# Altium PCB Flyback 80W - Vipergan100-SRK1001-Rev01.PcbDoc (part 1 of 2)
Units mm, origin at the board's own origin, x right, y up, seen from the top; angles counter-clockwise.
Board outline 121.92 x 39.12 mm, 2 copper layers (Top Layer, Bottom Layer), stack 1.58 mm thick; 100 components, 56 nets, 249 pads, 157 vias.
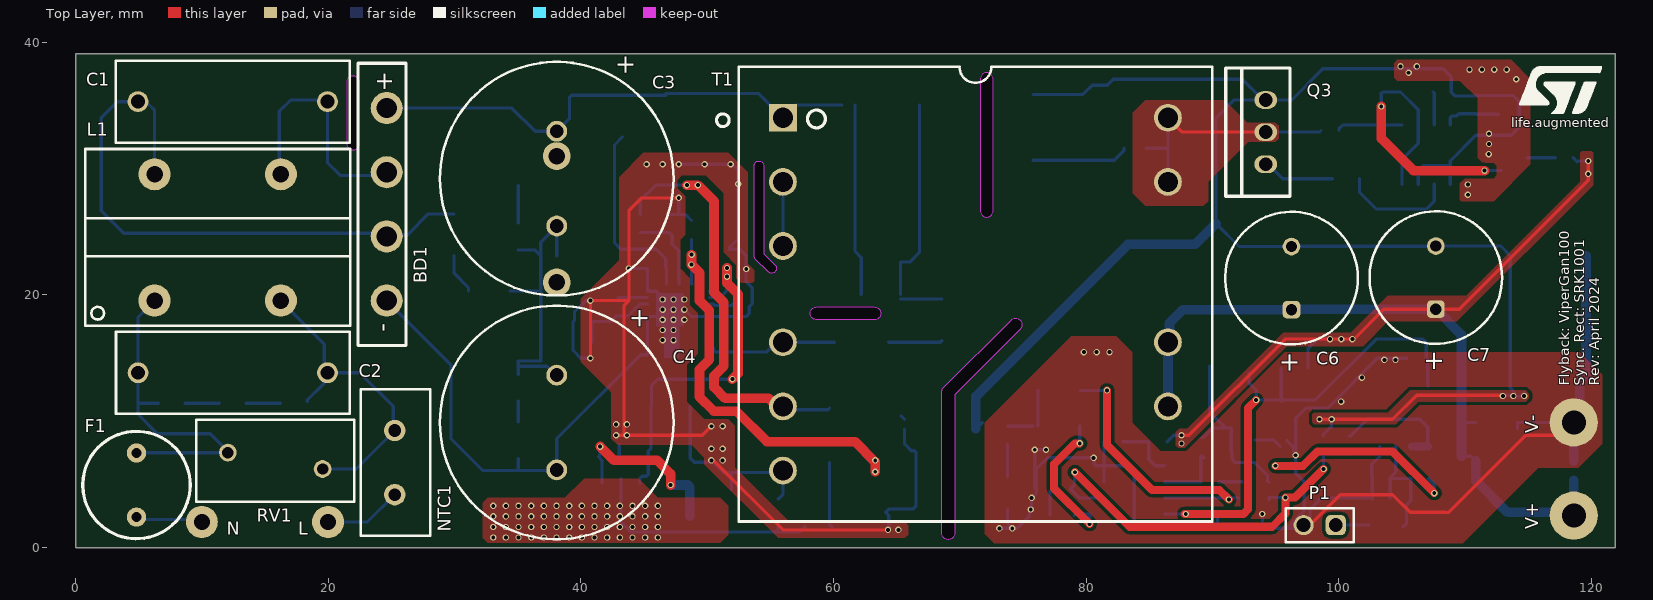
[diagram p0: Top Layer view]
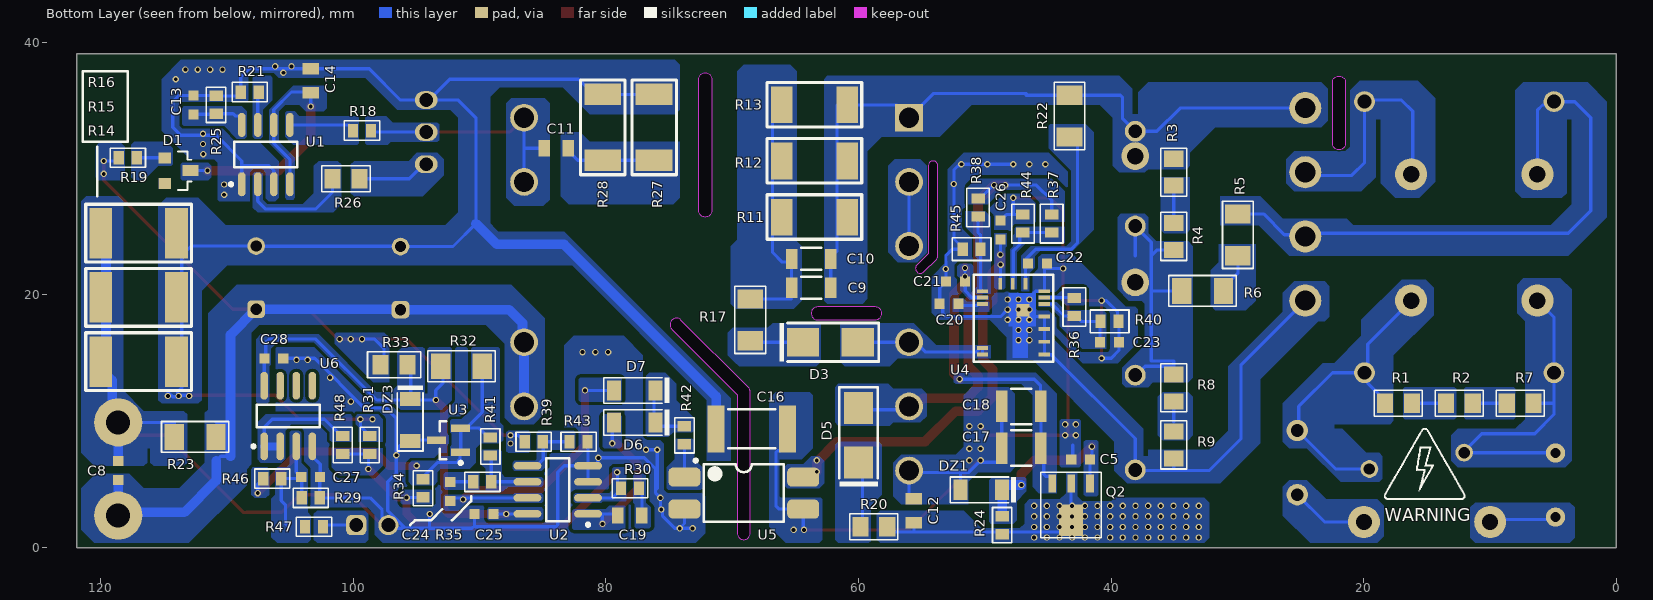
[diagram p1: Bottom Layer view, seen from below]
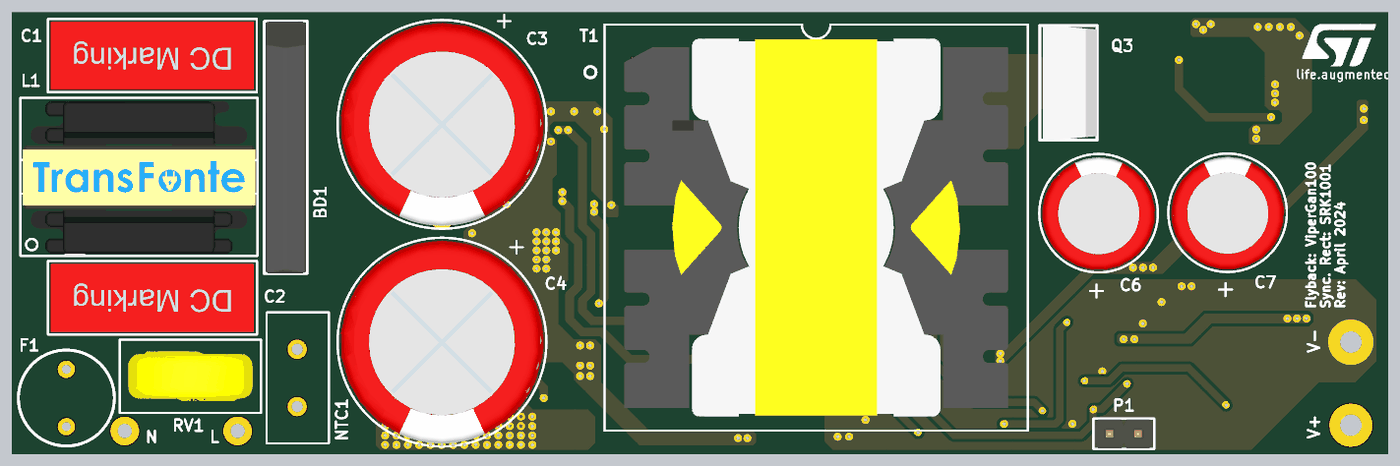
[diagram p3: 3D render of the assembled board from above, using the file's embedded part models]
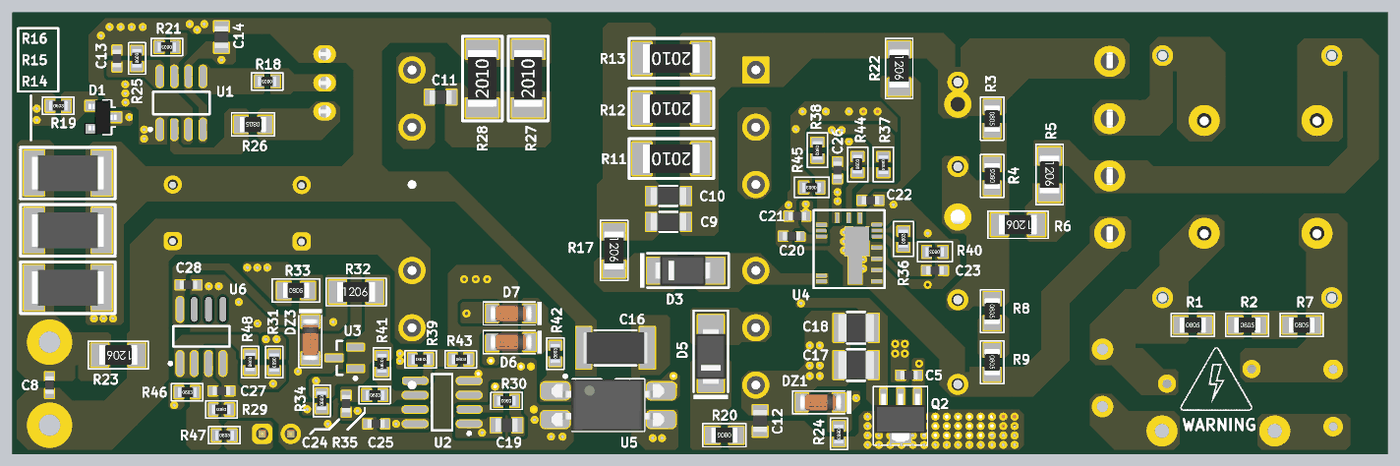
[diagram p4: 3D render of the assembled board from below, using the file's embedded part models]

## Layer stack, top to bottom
Top Solder: solder mask 0.0102, Solder Resist, Dk 3.5
Top Layer: signal copper 0.07
Dielectric 1: dielectric 1.44, FR-4, Dk 4.8
Bottom Layer: signal copper 0.07
Bottom Solder: solder mask 0.0102, Solder Resist, Dk 3.5

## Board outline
0,0 0,39.116 121.92,39.116 121.92,0
cut-out: 53.833,22.844 cw(c54.102,23.114) 53.721,23.114 53.721,30.226 cw(c54.102,30.226) 54.483,30.226 54.483,23.272 55.388,22.368 cw(c55.118,22.098) 55.499,22.098 cw(c55.118,22.098) 54.848,21.828
cut-out: 68.58,1.143 68.58,12.319 cw(c69.088,12.319) 68.729,12.679 68.729,12.678 74.063,18.012 cw(c74.422,17.653) 74.93,17.653 cw(c74.422,17.653) 74.781,17.294 69.596,12.108 69.596,1.143 cw(c69.088,1.143)
cut-out: 71.628,26.67 ccw(c72.136,26.67) 72.644,26.67 72.644,37.084 ccw(c72.136,37.084) 71.628,37.084
cut-out: 21.463,32.004 ccw(c21.971,32.004) 22.479,32.004 22.479,36.83 ccw(c21.971,36.83) 21.463,36.83
cut-out: 58.674,18.034 cw(c58.674,18.542) 58.674,19.05 63.246,19.05 cw(c63.246,18.542) 63.754,18.542 cw(c63.246,18.542) 63.246,18.034

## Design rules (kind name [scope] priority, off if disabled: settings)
Clearance Aux [InNet('Aux')] p1: gap=0.127 ignorepadtopadclearanceinfootprint=FALSE except(0: THPad-Hole Via-Hole Fill-Hole Poly-Hole Region-Hole Text-Hole; 0.305: Track-Poly Poly-Poly)
Clearance GND_Sec [InNet('GND-Sec')] p2: gap=0.203 ignorepadtopadclearanceinfootprint=TRUE except(0: THPad-Hole Via-Hole Fill-Hole Poly-Hole Region-Hole Text-Hole; 0.254: Arc-Poly Track-Poly SMDPad-Poly THPad-Poly Via-Poly Fill-Poly Poly-Poly Poly-Region Poly-Text)
Clearance GND_Out [InNet('GND-Out')] p3: gap=0.203 ignorepadtopadclearanceinfootprint=TRUE except(0: THPad-Hole Via-Hole Fill-Hole Region-Hole Text-Hole; 0.254: Arc-Poly Track-Poly SMDPad-Poly THPad-Poly Via-Poly Fill-Poly Poly-Poly Poly-Region Poly-Text Poly-Hole)
Clearance GND_Prim [InNet('GND-prim')] p4: gap=0.152 ignorepadtopadclearanceinfootprint=TRUE except(0: SMDPad-Hole THPad-Hole Via-Hole Fill-Hole Poly-Hole Region-Hole Text-Hole; 0.203: Track-Poly; 0.254: Poly-Poly)
Clearance Drain_PFC [InNet('Drain_PFC')] p5: gap=0.127 ignorepadtopadclearanceinfootprint=TRUE except(0: SMDPad-Hole THPad-Hole Via-Hole Fill-Hole Poly-Hole Region-Hole Text-Hole; 0.178: SMDPad-SMDPad; 0.203: SMDPad-Poly THPad-Poly Via-Poly Fill-Poly; 0.762: Arc-Track Arc-SMDPad Arc-THPad Arc-Poly Track-Track Track-SMDPad Track-THPad Track-Poly Poly-Poly)
Clearance Drain_Viper [InNet('Drain_Viper')] p6: gap=0.127 ignorepadtopadclearanceinfootprint=TRUE except(0: SMDPad-Hole THPad-Hole Via-Hole Fill-Hole Poly-Hole Region-Hole Text-Hole; 0.178: SMDPad-SMDPad; 0.203: Arc-Poly Track-Poly SMDPad-Poly THPad-Poly Via-Poly Fill-Poly Poly-Poly; 1.27: Arc-SMDPad Track-SMDPad)
Clearance [All] p7: gap=0.127 ignorepadtopadclearanceinfootprint=TRUE except(0: THPad-Hole Via-Hole Fill-Hole Poly-Hole Region-Hole Text-Hole)
Height [All] p1: minheight=0 maxheight=40 prefheight=26
MinimumSolderMaskSliver [All] p1: minsoldermaskwidth=0.076
PolygonConnect [All] p1: connectstyle=Direct reliefconductorwidth=0.254 reliefentries=4 polygonreliefangle="90 Angle" airgapwidth=0.254
RoutingVias [All] p1: holewidth=0.711 width=1.27 viastyle="Through Hole" minholewidth=0.305 minwidth=0.508 maxholewidth=0.711 maxwidth=1.27
SilkToSilkClearance [All] p1: silktosilkclearance=0.127
SilkToSolderMaskClearance [IsPad] p1: minsilkscreentomaskgap=0.076 clearancetoexposedcopper=TRUE
SolderMaskExpansion [All] p1: expansion=0.102 istentingtop=FALSE
Width [All] p1: maxlimit=0.762 minlimit=0.127 preferedwidth=0.254 minimp=50.000000 maximp=50.000000 favimp=50.000000
26 further rules are at their usual default settings.

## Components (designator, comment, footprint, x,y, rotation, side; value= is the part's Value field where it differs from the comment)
BD1 "4A/800V" GBU806 24.638,27.178 r270 top
C1 "220nF, 275V" WCAP-FTX2_L18W6H11.5 12.446,35.306 r180 top
C2 "220nF, 275V" WCAP-FTX2_L18W6H11.5 12.453,13.843 r180 top
C3 "150uF, 200V" WCAP-AT1H_18x25 38.1,29.21 r90 top locked
C4 "150uF, 200V" WCAP-AT1H_18x25 38.1,9.906 r90 top locked
C5 "NM" WCAP-CSGP_0603_H=0.8mm_Reflow 42.418,6.985 r180 bottom
C6 "330uF" WCAP-PTG5_D10H12.5 96.266,21.336 r270 top
C7 "330uF" WCAP-PTG5_D10H12.5 107.696,21.376 r270 top
C8 "100nF, 50V" WCAP-CSGP_0603_H=0.8mm_Reflow 118.618,6.096 r270 bottom
C9 "2.2nF, 630V" WCAP-CSMH_1206_H1.6 63.754,20.574 r180 bottom
C10 "2.2nF, 630V" WCAP-CSMH_1206_H1.6 63.754,22.86 r180 bottom
C11 "NM" WCAP-CSGP_0805_H=0.8mm_Reflow 83.947,31.623 r0 bottom
C12 "1nF, 200V" WCAP-CSMH_0805_H1.25 55.626,2.921 r270 bottom
C13 "NM" WCAP-CSGP_0603_H=0.8mm_Reflow 112.649,35.052 r270 bottom
C14 "1uF, 25V" WCAP-CSGP_0805_H=1.25mm 103.378,36.957 r270 bottom
C16 "2.2nF, 250V" WCAP-CSSA_2211_H2.5 68.453,9.398 r0 bottom
C17 "22uF, 25V" WCAP-CSGP_1210_H=2.5mm 47.117,7.874 r180 bottom
C18 "22uF, 25V" WCAP-CSGP_1210_H=2.5mm 47.117,11.176 r180 bottom
C19 "47nF, 25V" WCAP-CSGP_0805_H=0.8mm_Reflow 78.105,2.54 r0 bottom
C20 "1uF, 16V" WCAP-CSGP_0603_H=0.8mm_Reflow 52.832,19.304 r180 bottom
C21 "100nF, 50V" WCAP-CSGP_0603_H=0.8mm_Reflow 52.324,21.082 r180 bottom
C22 "220pF, 50V" WCAP-CSGP_0603_H=0.8mm_Reflow 45.847,22.479 r0 bottom
C23 "10nF, 25V" WCAP-CSGP_0603_H=0.8mm_Reflow 40.132,16.256 r0 bottom
C24 "220nF, 25V" WCAP-CSGP_0603_H=0.8mm_Reflow 92.329,4.445 r90 bottom
C25 "100nF, 50V" WCAP-CSGP_0603_H=0.8mm_Reflow 89.662,2.667 r180 bottom
C26 "4.7nF, 25V" WCAP-CSGP_0603_H=0.8mm_Reflow 48.768,25.146 r270 bottom
C27 "470nF, 25V" WCAP-CSGP_0603_H=0.8mm_Reflow 103.378,5.588 r0 bottom
C28 "100nF, 50V" WCAP-CSGP_0603_H=0.8mm_Reflow 106.3,14.986 r0 bottom
D1 "BAS21" SOT23_Single 113.919,29.845 r270 bottom value=250V/200mA
D3 "STTH2L06A" SMA 62.23,16.256 r180 bottom value=1A/600V
D5 "STTH1L06A" SMA 60,8.89 r90 bottom value=1A/600V
D6 "LL4148" SOD80 77.724,9.906 r0 bottom value="100V 150mA"
D7 "LL4148" SOD80 77.724,12.446 r0 bottom value="100V 150mA"
DZ1 "TZM5245B-GS08" SOD80 50.292,4.572 r0 bottom value=15V/0.5W
DZ3 "NM" SOD80 95.504,10.1 r270 bottom
F1 "4A/250Vac" MRT 4.826,4.953 r90 top
L "Line" Pin_Hole_50mil 20,2.032 r0 top
L1 "YEF20V-4P10MH" EF20VCD4T-F 6.256,19.558 r90 top
N "Neutral" Pin_Hole_50mil 10,2.032 r0 top
NTC1 "2.2Ω" D11.5xW5.0xH16.0xL5.0 25.273,6.731 r90 top value="2.2Ω, 6 / 5A"
P1 "61300211121" 61300211121 98.5,1.778 r180 top
Q2 "ZXTN4006ZTA" "SOT-89 - BCE" 43.18,5.08 r0 bottom value=200V/1A
Q3 "FDP075N15A_F102" NFET_TO220FP 94.234,30.353 r90 top
R1 "TBD" 0805 17.272,11.43 r180 bottom
R2 "TBD" 0805 12.446,11.43 r180 bottom
R3 "1M5 ± 5%" 0805 35.052,29.718 r270 bottom
R4 "1M5 ± 5%" 0805 35.052,24.638 r90 bottom
R5 "0R" 1206 29.972,24.765 r270 bottom
R6 "0R" 1206 32.766,20.32 r0 bottom
R7 "TBD" 0805 7.62,11.43 r180 bottom
R8 "1M5 ± 5%" 0805 35.052,12.649 r270 bottom
R9 "1M5 ± 5%" 0805 35.052,8.128 r270 bottom
R11 "470K ± 5%" 2010 63.5,26.162 r0 bottom
R12 "470K ± 5%" 2010 63.5,30.607 r0 bottom
R13 "470K ± 5%" 2010 63.5,35.052 r0 bottom
R14 "22 mOhm ±1%" 2512 117,14.732 r0 bottom
R15 "22 mOhm ±1%" 2512 117,19.812 r0 bottom
R16 "22 mOhm ±1%" 2512 117,24.892 r0 bottom
R17 "20R ± 1%" 1206 68.58,18.034 r270 bottom
R18 "330R ± 5%" "0603 - teste" 99.314,33.02 r0 bottom
R19 "0R" "0603 - teste" 117.856,30.861 r180 bottom
R20 "47R ± 5%" 0805 58.801,1.651 r0 bottom
R21 "75K ± 5%" "0603 - teste" 108.204,36.068 r0 bottom
R22 "10M ± 1%" 1206 43.307,34.163 r270 bottom
R23 "NM" 1206 112.522,8.763 r0 bottom
R24 "39K ± 5%" "0603 - teste" 48.641,1.778 r270 bottom
R25 "75K ± 5%" "0603 - teste" 110.871,35.052 r90 bottom
R26 "0R" 0805 100.584,29.21 r0 bottom
R27 "NM 2010" 2010 76.2,33.274 r90 bottom
R28 "NM 2010" 2010 80.264,33.274 r90 bottom
R29 "180K ± 5%" "0603 - teste" 103.378,3.937 r0 bottom
R30 "22K ± 5%" "0603 - teste" 78.105,4.699 r0 bottom
R31 "1K5 ± 1%" "0603 - teste" 98.7,8.128 r270 bottom
R32 "2K2 ± 5%" 1206 91.44,14.351 r180 bottom
R33 "0R" SM/R_0805 96.774,14.478 r180 bottom
R34 "1M ± 5%" "0603 - teste" 94.488,4.699 r90 bottom
R35 "47K ± 5%" "0603 - teste" 89.789,5.207 r180 bottom
R36 "61K9" SM/R_0603 42.926,19.05 r90 bottom
R37 "820K" SM/R_0603 44.704,25.654 r270 bottom
R38 "560K" SM/R_0603 50.546,26.924 r270 bottom
R39 "130K ± 1%" "0603 - teste" 85.725,8.382 r180 bottom
R40 "20K5" SM/R_0603 40.132,17.907 r0 bottom
R41 "10K ± 5%" "0603 - teste" 89.154,8.001 r90 bottom
R42 "1K ± 5%" "0603 - teste" 73.787,8.89 r90 bottom
R43 "18K2 ± 1%" "0603 - teste" 82.169,8.382 r180 bottom
R44 "15K" SM/R_0603 46.99,25.654 r90 bottom
R45 "15K" SM/R_0603 51.054,23.622 r0 bottom
R46 "NM ± 1%" "0603 - teste" 106.426,5.461 r180 bottom
R47 "1K ± 5%" "0603 - teste" 103.124,1.651 r180 bottom
R48 "26K1 ± 1%" "0603 - teste" 100.838,8.128 r90 bottom
RV1 "820512711" D12.5xW6.5xH16xP1.3 15.808,6.873 r0 top
T1 "YPQ3220V-12P435UH" PQ3220_Trigon 71.247,20.066 r0 top locked
U1 "SRK1001" SO8_L 106.934,31.115 r90 bottom
U2 "LM2904D" SO8_N 83.82,4.572 r0 bottom
U3 "TL431AIL3T" SOT23-3_N 92.456,8.509 r0 bottom
U4 "ViperGan100TR" "VIPERGAN - ISAC" 45.29,14.796 r0 bottom locked value="QR Controller"
U5 "FOD817AS" SO-4 69.088,4.318 r180 bottom
U6 "LM2904D" SO8_N 105.156,10.414 r90 bottom
V+ "Vout" Pin_Hole_75mil 118.618,2.54 r0 top
V- "GND" Pin_Hole_75mil 118.618,9.906 r0 top

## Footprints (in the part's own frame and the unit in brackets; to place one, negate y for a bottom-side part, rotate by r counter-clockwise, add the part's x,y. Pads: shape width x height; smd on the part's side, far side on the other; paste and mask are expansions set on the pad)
"0603 - teste" [mil] "SMD Chip Resistor, 125 mW, 0603 [1608 Metric], Thick Film, General Purpose"
  rect 32x42 smd: 1(-28,0) 2(28,0)
  silkscreen extent -55,-30 55,30, body extent -31,-17 33,17, height 16
0805 [mil] "SMD Chip Resistor, 200 mW, 0805 [2012 Metric], Thick Film, General Purpose"
  rect 50x60 smd: 1(-42,0) 2(42,0)
  silkscreen extent -75,-41 75,41, body extent -45,-27 45,27, height 30
1206 [mil] "SMD Chip Resistor, 250 mW, 1206 [3216 Metric], Thick Film, General Purpose"
  rect 60x80 smd: 1(-65,0) 2(65,0)
  silkscreen extent -105,-48 105,48, body extent -66,-34 66,34, height 33
2010 [mm] "'SMD Chip Resistor, 1W, 2010, Thick Film, General Purpose"
  rect 1.7x2.9 smd: 1(-2.6,0) 2(2.6,0)
  silkscreen extent -3.75,-1.78 3.75,1.75, body extent -2.5,-1.25 2.5,1.25, height 0.6
2512 [mm] "SMD Chip Resistor, 2W, 2512, Thick Film, General Purpose"
  rect 1.8x4 smd: 1(-2.997,0) 2(2.997,0)
  silkscreen extent -4.19,-2.29 4.19,2.29, body extent -3.17,-1.59 3.18,1.59, height 0.5
61300211121 [mm] "Pin Header, pitch 2.54 mm, THT, Vertical, single row, 2p"
  rrect50% 1.6x1.6 hole 1.1: 1(-1.27,0)
  round 1.6 hole 1.1: 2(1.27,0)
  silkscreen extent -2.69,-1.35 2.69,1.35, body extent -2.54,-1.27 2.54,1.27, height 8.57
D11.5xW5.0xH16.0xL5.0 [mm] "Inrush Current Limiter, Diameter 11.5mm, Width 5.0mm, Height 16.0mm, Leads 5.0mm"
  round 1.7 hole 1: 1(-2.54,0) 2(2.54,0)
  silkscreen extent -5.8,-2.8 5.8,2.7, body extent -5.75,-2.5 5.75,2.5, height 13.75
D12.5xW6.5xH16xP1.3 [mm] "Disk Varistor, Diameter 12.5mm, Width 6.5mm"
  round 1.4 hole 0.9: 1(-3.75,0.65) 2(3.75,-0.65)
  silkscreen extent -6.25,-3.25 6.25,3.25, body extent -5.5,-2.2 5.5,2.2, height 13.4
EF20VCD4T-F [mm]
  round 2.54 hole 1.3: 1(0,0) 2(0,-10) 3(10,-10) 4(10,0)
  silkscreen extent -2,-15.5 12,5.5, body extent -2,-15.3 11.7,5.3, height 21.48
GBU806 [mm]
  round 2.54 / inner round 1.524 / far side round 2.54 hole 1.6: 1(-7.62,0) 2(-2.54,0) 3(2.54,0) 4(7.62,0)
  silkscreen extent -11.18,-2.29 11.18,1.52, body extent -11.15,-2.16 11.15,1.4, height 20.83
MRT [mil]
  round 60 hole 31.5: 1(-100,0) 2(100,0)
  silkscreen extent -167,-167 167,167, body extent -165,-167 170,167, height 315
NFET_TO220FP [mm]
  oval 1.4x1.8 hole 1.1: D(2.54,0) G(0,0) S(5.08,0)
  silkscreen extent -2.54,-1.91 7.62,3.18, body extent -2.54,-1.91 7.62,2.89, height 19.3
Pin_Hole_50mil [mm]
  round 2.54 hole 1.27: 1(0,0)
Pin_Hole_75mil [mm]
  round 3.81 hole 1.905: 1(0,0)
PQ3220_Trigon [mm] "THT, Body 35.56x37.34mm, 12Pins,Pitch 5.08mm"
  rect 2.2x2.2 hole 1.6: 1(-15.24,13.97)
  round 2.2 hole 1.6: 2(-15.24,8.89) 3(-15.24,3.81) 4(-15.24,-3.81) 5(-15.24,-8.89) 6(-15.24,-13.97) 8(15.24,-8.89) 9(15.24,-3.81) 11(15.24,8.89) 12(15.24,13.97)
  silkscreen extent -20.5,-18 18.75,18, body extent -17,-16.75 17,16.75, height 20.92
SM/R_0603 [mil]
  rect 32x42 smd: 1(-28,0) 2(28,0)
  silkscreen extent -60,-36 60,35, body extent -31,-17 33,17, height 16
SM/R_0805 [mil]
  rect 50x60 smd: 1(-42,0) 2(42,0)
  silkscreen extent -83,-41 83,41, body extent -45,-26 45,27, height 30
SMA [mil]
  rect 100x90 smd: A(85,0) K(-85,0)
  silkscreen extent -159,-60 150,60, body extent -108,-53 88,53, height 95
SO8_L [mm] "SOIC, 8-Leads, Body 4.9x3.9mm, Pitch 1.27mm, IPC High Density"
  oval 1.9x0.6 smd: 1(-2.35,1.905) 2(-2.35,0.635) 3(-2.35,-0.635) 4(-2.35,-1.905) 5(2.35,-1.905) 6(2.35,-0.635) 7(2.35,0.635) 8(2.35,1.905)
  silkscreen extent -2.47,-2.5 1,2.88, body extent -2,-2.5 2,2.5, height 1.75
SO8_N [mm] "SOIC, 8-Leads, Body 4.9x3.9mm, Pitch 1.27mm, IPC Medium Density"
  oval 2.2x0.6 smd: 1(-2.4,1.905) 2(-2.4,0.635) 3(-2.4,-0.635) 4(-2.4,-1.905) 5(2.4,-1.905) 6(2.4,-0.635) 7(2.4,0.635) 8(2.4,1.905)
  silkscreen extent -2.52,-2.5 0.9,2.88, body extent -2,-2.5 2,2.5, height 1.75
SO-4 [mil]
  rrect50% 100x60 smd: 1(-185,50) 2(-185,-50) 3(185,-50) 4(185,50)
  silkscreen extent -155,-90 125,106, body extent -199,-90 195,90, height 152
SOD80 [mm] "LL4148"
  rect 1.1x1.6 smd: A(1.65,0) K(-1.65,0)
  silkscreen extent -2.74,-1.02 2.45,1.02, body extent -1.88,-0.8 1.82,0.8, height 1.6
SOT23-3_N [mm] "SOT23, 3-Leads, Body 2.9x1.3mm, Pitch 0.95mm, Lead Span 2.4mm, IPC Medium Density"
  rect 1.5x0.6 smd: 1(-0.95,0.95) 2(-0.95,-0.95) 3(0.95,0)
  silkscreen extent -1.07,-1.5 0.7,1.92, body extent -0.7,-1.52 0.7,1.52, height 1.12
SOT23_Single [mil]
  rect 34x40 smd: A(-40,-40) NC(40,-40)
  rect 34x50 smd: K(0,40)
  silkscreen extent -60,1 60,44, body extent -59,-49 59,49, height 42
"SOT-89 - BCE" [mm]
  rect 0.6x1.4 smd: B(-1.5,0) C(0,0) E(1.5,0)
  rect 1.9x2.5 smd: C(0,2.9)
  silkscreen extent -2.4,-0.9 2.4,4.3, body extent -2.25,-0.25 2.25,4, height 1.54
"VIPERGAN - ISAC" [mm]
  rect 0.9x0.3 smd mask+0.05: 1(0,-0.5) 2(0,-1.5) 3(0,-2.5) 4(0,-3.5) 5(0,-4.5) 6(0,-5) 7(0,-5.5) 11(4.9,-5.5) 12(4.9,-5) 13(4.9,-4.5) 15(4.9,-1) 16(4.9,-0.5)
  rect 0.3x0.9 smd mask+0.05: 8(1.5,-6.1) 9(2.5,-6.1) 10(3.5,-6.1)
  rect 1x1 smd paste+0: EP(1.7,-4)
  Top Layer region: 0.675,-5.341 2.829,-5.341 2.829,-2.741 2.524,-2.741 2.524,-0.241 1.3,-0.241 1.3,-2.741 0.675,-2.741
  silkscreen extent -0.7,-6.8 5.6,0.1, body extent 0,-6 5,0, height 0.58
WCAP-AT1H_18x25 [mm] "Aluminium Electrolytic Radial THD Capacitors, 18x25mm"
  round 1.65 hole 1.1: 1(-3.75,0) 2(3.75,0)
  silkscreen extent -9.25,-9.25 9.25,9.25, body extent -8.99,-9 9,9, height 25.26
WCAP-CSGP_0603_H=0.8mm_Reflow [mm] "Ceramic Capacitors, body 1.6x0.8mm"
  rect 0.8x0.8 smd: 1(-0.75,0) 2(0.75,0)
  body extent -0.8,-0.4 0.8,0.4, height 0.8
WCAP-CSGP_0805_H=0.8mm_Reflow [mm] "Ceramic Capacitors, body 2x1.25mm"
  rect 0.9x1.3 smd: 1(-0.95,0) 2(0.95,0)
  body extent -1,-0.62 1,0.63, height 0.8
WCAP-CSGP_0805_H=1.25mm [mm] "Ceramic Capacitors, body 2x1.25mm"
  rect 0.9x1.3 smd: 1(-0.95,0) 2(0.95,0)
  body extent -1,-0.62 1,0.63, height 1.25
WCAP-CSGP_1210_H=2.5mm [mm] "Ceramic Capacitors, body 3.2x2.5mm"
  rect 0.9x2.5 smd: 1(-1.55,0) 2(1.55,0)
  silkscreen extent -0.8,-1.4 0.8,1.4, body extent -1.6,-1.25 1.6,1.25, height 2.5
WCAP-CSMH_0805_H1.25 [mm] "Ceramic Capacitors, body 2x1.25mm"
  rect 0.9x1.3 smd: 1(-0.95,0) 2(0.95,0)
  body extent -1,-0.62 1,0.63, height 1.25
WCAP-CSMH_1206_H1.6 [mm] "Ceramic Capacitors, body 3.2x1.6mm"
  rect 0.9x1.6 smd: 1(-1.55,0) 2(1.55,0)
  silkscreen extent -0.8,-0.87 0.8,0.87, body extent -1.6,-0.8 1.6,0.8, height 1.6
WCAP-CSSA_2211_H2.5 [mm] "Ceramic Capacitors, body 5.7x2.8mm"
  rect 1.35x3.7 smd: 1(-2.825,0) 2(2.825,0)
  silkscreen extent -1.85,-1.55 1.85,1.55, body extent -2.85,-1.4 2.85,1.4, height 2.5
WCAP-FTX2_L18W6H11.5 [mm] "Film Capacitors, 18x6x11.5mm"
  round 1.65 hole 1.1: 1(-7.5,0) 2(7.5,0)
  silkscreen extent -9.25,-3.25 9.25,3.25, body extent -9,-3 9,3, height 11.55
WCAP-PTG5_D10H12.5 [mm] "Aluminum Polymer Capacitors, 10x12.5mm"
  rrect50% 1.4x1.4 hole 0.9: 1(2.5,0)
  round 1.4 hole 0.9: 2(-2.5,0)
  silkscreen extent -5.25,-5.25 5.25,5.25, body extent -4.95,-4.99 5,4.99, height 12.81

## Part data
BD1: library part GBU806, "800V 4A GBL Single Phase Bridge Rectifier", Forward Current=4A, Manufacturer="Diodes Inc", Manufacturer Part Number=GBU8J, Max Forward Surge Current (Ifsm)=150A, Max Operating Temperature=150°C, Max Repetitive Reverse Voltage (Vrrm)=800V, Max Reverse Current=5uA, Min Operating Temperature=-55°C, Package Quantity=1000, Package/Class="Full wave bridge", Supplier Part Number 1=GBU806DI-ND
C1 C2: library part 890324025027, "WCAP-FTX2 Film Capacitor, THT, L18W6H11.5, 220nF, 275V", Capacitance=220nF, Capacitance Tolerance=+/-10%, Insulation Resistance=30000MOhm, Manufacturer="Wurth Elektronik", Operating Temperature="-40 to +105degC", Rate of Voltage Rise=180V/us, Rated Voltage=275VAC
C3 C4: library part 860241081008, "WCAP-AT1H Aluminum Electrolytic Capacitor, Radial, THT, D18xH25mm, 150uF, 200V", Capacitance=150uF, Capacitance Tolerance=+/-20%, Leakage Current=1300uA, Manufacturer="Wurth Elektronik", Operating Temperature="-25 to +105degC", Rated Voltage=200VDC, Ripple Current=1800mA
C5 C8 C21 C25 C28: library part 885012206095, "WCAP-CSGP Multilayer Ceramic Chip Capacitor, General Purpose, size 0603, X7R, 100nF, 50V", Capacitance=100nF, Capacitance Tolerance=+/-10%, Isolation Resistance=>{}5GOhm, Manufacturer="Wurth Elektronik", Operating Temperature="-55 to +125degC", Rated Voltage=50VDC
C6 C7: library part 870025575009, "WCAP-PTG5 Aluminum Polymer Capacitor, Radial THT, D10xH12.5mm, 330uF, 25V", Capacitance Tolerance=+/-20%, Leakage Current=1650uA, Manufacturer="Wurth Elektronik", Operating Temperature Max=105°C, Operating Temperature Min=-55°C, Rated Voltage (DC)=25V, Ripple Current=4900mA
C9 C10: library part 885342008007, "WCAP-CSMH Multilayer Ceramic Chip Capacitor, size 1206, NP0 Class I, 2.2nF, 630V", Capacitance=2.2nF, Capacitance Tolerance=+/-5%, Insulation Resistance=10GOhm, Manufacturer="Wurth Elektronik", Operating Temperature="-55 to +125degC", Rated Voltage=630VDC
C11: library part 885012207119, "WCAP-CSGP Multilayer Ceramic Chip Capacitor, General Purpose, size 0805, X7R, 3.3nF, 100V", Capacitance=3.3nF, Capacitance Tolerance=+/-10%, Isolation Resistance=>{}10GOhm, Manufacturer="Wurth Elektronik", Operating Temperature="-55 to +125degC", Rated Voltage=100VDC
C12: library part 885342007003, "WCAP-CSMH Multilayer Ceramic Chip Capacitor, size 0805, NP0 Class I, 1nF, 200V", Capacitance=1nF, Capacitance Tolerance=+/-5%, Insulation Resistance=10GOhm, Manufacturer="Wurth Elektronik", Operating Temperature="-55 to +125degC", Rated Voltage=200VDC
C13: library part 885012206071, "WCAP-CSGP Multilayer Ceramic Chip Capacitor, General Purpose, size 0603, X7R, 100nF, 25V", Capacitance=100nF, Capacitance Tolerance=+/-10%, Isolation Resistance=>{}5GOhm, Manufacturer="Wurth Elektronik", Operating Temperature="-55 to +125degC", Rated Voltage=25VDC
C14: library part 885012207078, "WCAP-CSGP Multilayer Ceramic Chip Capacitor, General Purpose, size 0805, X7R, 1uF, 25V", Capacitance=1uF, Capacitance Tolerance=+/-10%, Isolation Resistance=>{}0.5GOhm, Manufacturer="Wurth Elektronik", Operating Temperature="-55 to +125degC", Rated Voltage=25VDC
C16: library part 885352213015, "WCAP-CSSA Multilayer Ceramic Chip Safety Capacitor, size 2211, X1/Y2, 2.2nF, 250V", Capacitance=2.2nF, Capacitance Tolerance=+/-10%, Impulse Voltage=5000VDC, Isolation Resistance=10GOhm, Manufacturer="Wurth Elektronik", Operating Temperature="-55 to +125degC", Rated Voltage=250VAC
C17 C18: library part 885012209074, "WCAP-CSGP Multilayer Ceramic Chip Capacitor, General Purpose, size 1210, X7R, 22uF, 25V", Capacitance=22uF, Capacitance Tolerance=+/10%, Isolation Resistance=>{}0.005GOhm, Manufacturer="Wurth Elektronik", Operating Temperature="-55 to +125degC", Rated Voltage=25VDC
C19: library part 885012207070, "WCAP-CSGP Multilayer Ceramic Chip Capacitor, General Purpose, size 0805, X7R, 47nF, 25V", Capacitance=47nF, Capacitance Tolerance=+/-10%, Isolation Resistance=>{}10GOhm, Manufacturer="Wurth Elektronik", Operating Temperature="-55 to +125degC", Rated Voltage=25VDC
C20: library part 885012106017, "WCAP-CSGP Multilayer Ceramic Chip Capacitor, General Purpose, size 0603, X5R, 1uF, 16V", Capacitance=1uF, Capacitance Tolerance=+/-20%, Isolation Resistance=>{}0.1GOhm, Manufacturer="Wurth Elektronik", Operating Temperature="-55 to +85degC", Rated Voltage=16VDC
C22: library part 885012206079, "WCAP-CSGP Multilayer Ceramic Chip Capacitor, General Purpose, size 0603, X7R, 220pF, 50V", Capacitance=220pF, Capacitance Tolerance=+/-10%, Isolation Resistance=>{}10GOhm, Manufacturer="Wurth Elektronik", Operating Temperature="-55 to +125degC", Rated Voltage=50VDC
C23: library part 885012206065, "WCAP-CSGP Multilayer Ceramic Chip Capacitor, General Purpose, size 0603, X7R, 10nF, 25V", Capacitance=10nF, Capacitance Tolerance=+/-10%, Isolation Resistance=>{}10GOhm, Manufacturer="Wurth Elektronik", Operating Temperature="-55 to +125degC", Rated Voltage=25VDC
C24 C27: library part 885012206075, "WCAP-CSGP Multilayer Ceramic Chip Capacitor, General Purpose, size 0603, X7R, 470nF, 25V", Capacitance=470nF, Capacitance Tolerance=+/-10%, Isolation Resistance=>{}1.1GOhm, Manufacturer="Wurth Elektronik", Operating Temperature="-55 to +125degC", Rated Voltage=25VDC
C26: library part 885012206063, "WCAP-CSGP Multilayer Ceramic Chip Capacitor, General Purpose, size 0603, X7R, 4.7nF, 25V", Capacitance=4.7nF, Capacitance Tolerance=+/-10%, Isolation Resistance=>{}10GOhm, Manufacturer="Wurth Elektronik", Operating Temperature="-55 to +125degC", Rated Voltage=25VDC
D1: "Fast Switching Diode.", Manufacturer=Diodes, Package=SOT-23
D3: library part SMA, "600 V, 2 A Low Drop Ultrafast Diode.", Manufacturer=STMicroelectronics
D5: library part SMA, "600 V, 1 A Low Drop Ultrafast Diode.", Manufacturer=STMicroelectronics
D6 D7: "Small Signal Diode", Manufacturer=Vishay, Manufacturer Part Number=LL4148-M-18, Package=SOD123
DZ1: library part TZM52xxB, "Small Signal Zener Diodes, 5%, 500mW", Manufacturer=Vishay, Package=SOD-80
DZ3: library part SOD80_zener
F1: library part Fuse, "FUSE BOARD MOUNT 4A 250VAC RAD", Case/Package=Radial, Color=Brown, Current Rating=4A, DC Cold Resistance=18.52mR, Flammability Rating="UL94 V-0", Manufacturer="Littelfuse Wickmann", Manufacturer Part Number=37314000410, Max Operating Temperature=85°C, Min Operating Temperature=-40°C, Package Quantity=1000, Power Dissipation=520mW, Supplier Part Number 1=WK3062BK-ND, Voltage Rating (AC)=250V
L N: library part Pin_Hole_50mil
L1: library part EF20VCD4T-F_Transfonte_Esquema2, Manufacturer="Trigon Components"
NTC1: library part B57236S0229M000, "Inrush Current Limiter, Diameter 11.5mm, Width 5.0mm, Height 16.0mm, Leads 5.0mm, 2.2Ω, 6 / 5A", Manufacturer=TDK, Max. Current="6 / 5A", Resistance Tolerance=±20%
P1: "WR-PHD Pin Header, THT, Vertical, pitch 2.54mm, 1 Row, 2P", Contact Resistance=20mΩ, Manufacturer="Wurth Elektronik", Operating Temperature Max=105°C, Operating Temperature Min=-40°C, Rated Current=3A, Withstanding Voltage=500V, Working Voltage=250V
Q2: library part NPN, "200V, 1A NPN LED DRIVING TRANSISTOR IN SOT89", Manufacturer=Diodes, Package=SOT89
Q3: library part NFET, "N-Channel Mosfet, 150V, 130A, 7.5m Ohms.", Manufacturer=ONSEMI, Package=TO-220
R1 R2 R3 R4 R7 R8 R9 R20 R26: library part 0805, "SMD Chip Resistor, 200 mW, 0805 [2012 Metric], Thick Film, General Purpose", Manufacturer=Any, Resistor Type="FIXED RESISTOR"
R5 R6 R17 R23 R32: library part 1206, "SMD Chip Resistor, 250 mW, 1206 [3216 Metric], Thick Film, General Purpose", Manufacturer=Any, Resistor Type="FIXED RESISTOR"
R11 R12 R13: library part 2010, "SMD Chip Resistor, 1W, 2010, Thick Film, General Purpose", Manufacturer=Yageo, Manufacturer Part Number=RC2010JK-07470KL, Resistor Type="FIXED RESISTOR"
R14 R15 R16: library part 2512, "SMD Chip Resistor, 2512, High Power Metal Strip Resistors for Current Sensing.", Manufacturer="TE Connectivity", Manufacturer Part Number=TLRP3A30DR022FTE, Resistor Type="FIXED RESISTOR"
R18: library part 0603, "SMD Chip Resistor, 125 mW,  0603 [1608 Metric] 330 Ohm, Thick Film, General Purpose", Manufacturer=Any, Resistor Type="FIXED RESISTOR"
R19 R21 R24 R25 R29 R30 R31 R34 R35 R39 R41 R42 R43 R46 R47 R48: library part 0603, "SMD Chip Resistor, 125 mW, 0603 [1608 Metric], Thick Film, General Purpose", Manufacturer=Any, Resistor Type="FIXED RESISTOR"
R22: library part 1206, "SMD Chip Resistor, 250 mW, 1206 [3216 Metric], Thick Film, General Purpose", Manufacturer=Bourns, Manufacturer Part Number=CHV1206-FX-1005ELF, Resistor Type="FIXED RESISTOR"
R27 R28: library part 2010, "SMD Chip Resistor, 1W, 2010, Thick Film, General Purpose", Manufacturer=Any, Resistor Type="FIXED RESISTOR"
R33: library part SMRes, "Res Thick Film 1206 10 Ohm 1% 1/4W ±100ppm/°C Molded SMD SMD Paper T/R", Case Code (Imperial)=1206, Case Code (Metric)=3216, Manufacturer Part Number=CRCW1206-10R0FKEA, Max Operating Temperature=155°C, Max Power Dissipation=250mW, Min Operating Temperature=-55°C, Package Quantity=10, Resistance=10R, Resistance Tolerance=1%, Resistor Type="FIXED RESISTOR", Supplier Part Number 1=52X0976, Temperature Coefficient=100ppm/°C, Voltage Rating=200V
R36: library part SMRes, "Res Thick Film 0603 61.9K Ohm 1% 1/10W ±100ppm/°C Molded SMD SMD Paper T/R", Case Code (Imperial)=0603, Case Code (Metric)=1608, Manufacturer=Any, Manufacturer Part Number=CRCW060356K0FKEA, Max Operating Temperature=155°C, Max Power Dissipation=100mW, Min Operating Temperature=-55°C, Package Quantity=10, Resistance=61.9K, Resistance Tolerance=1%, Resistor Type="FIXED RESISTOR", Supplier Part Number 1=6790548, Temperature Coefficient=100ppm/°C, Voltage Rating=75V
R37: library part SMRes, "Res Thick Film 0603 180K Ohm 1% 1/10W ±100ppm/°C Molded SMD SMD Paper T/R", Case Code (Imperial)=0603, Case Code (Metric)=1608, Manufacturer Part Number=CRCW0603180KFKEA, Max Operating Temperature=155°C, Max Power Dissipation=100mW, Min Operating Temperature=-55°C, Package Quantity=10, Resistance=180kR, Resistance Tolerance=1%, Resistor Type="FIXED RESISTOR", Temperature Coefficient=100ppm/°C, Voltage Rating=75V
R38: library part SMRes, "Res Thick Film 0603 120K Ohm 1% 0.1W(1/10W) ±100ppm/°C Pad SMD Automotive T/R", Case Code (Imperial)=0603, Case Code (Metric)=1608, Manufacturer Part Number=CRCW0603120KFKEA, Max Operating Temperature=155°C, Max Power Dissipation=100mW, Min Operating Temperature=-55°C, Package Quantity=5000, Resistance=120kR, Resistance Tolerance=1%, Resistor Type="FIXED RESISTOR", Supplier Part Number 1=6789715, Temperature Coefficient=100ppm/°C, Voltage Rating=75V
R40: library part SMRes, "Res Thick Film 0603 20.5K Ohm 1% 1/10W ±100ppm/°C Molded SMD Paper T/R", Case Code (Imperial)=0603, Case Code (Metric)=1608, Manufacturer=Any, Manufacturer Part Number=CRCW060315K0FKEA, Max Operating Temperature=155°C, Max Power Dissipation=100mW, Min Operating Temperature=-55°C, Package Quantity=5000, Resistance Tolerance=1%, Resistor Type="FIXED RESISTOR", Supplier Part Number 1=6789793, Temperature Coefficient=100ppm/°C, Voltage Rating=75V
R44 R45: library part SMRes, "Res Thick Film 0603 15K Ohm 1% 1/10W ±100ppm/°C Molded SMD Paper T/R", Case Code (Imperial)=0603, Case Code (Metric)=1608, Manufacturer Part Number=CRCW060315K0FKEA, Max Operating Temperature=155°C, Max Power Dissipation=100mW, Min Operating Temperature=-55°C, Package Quantity=5000, Resistance=15kR, Resistance Tolerance=1%, Resistor Type="FIXED RESISTOR", Supplier Part Number 1=6789793, Temperature Coefficient=100ppm/°C, Voltage Rating=75V
RV1: "WE-VD Disk Varistor, D12.5mm, W6.5mm, H16mm, 275VAC, 350VDC", (Channel) Input Capacitance=190pF, (Reverse) Breakdown Voltage=430V, (Reverse) Peak Pulse Current=2500A, AC Operating Voltage=275V, Clamping Voltage=710V, DC Operating Voltage=350V, Manufacturer="Wurth Elektronik", Operating Temperature="-40 to +85degC", Power Dissipation=0.4W
T1: library part "PQ3220, ViperGan100", "Transformer 12-Terminal , THT, Vertical, PQ Style Bobbins, PQ3220", Manufacturer="Trigon Components", Package=PQ3220
U1: "Adaptive synchronous rectification controller for flyback converter", Manufacturer=STMicroelectronics
U2 U6: "Low-Power Dual Operational Amplifier"
U3: "STMICROELECTRONICS - TL431AIL3T - Voltage Reference, AEC-Q100, Shunt - Adjustable, 2.5V to 36V, 1 % Ref, SOT-23-3", Case/Package=SOT-23-3, Cathode Current=700uA, Manufacturer=STMicroelectronics, Max Input Voltage=37V, Max Operating Temperature=105°C, Max Output Current=100mA, Max Output Voltage=36V, Min Operating Temperature=-40°C, Package Quantity=1, Reference Voltage=2.495V, Supplier Part Number 1=497-11295-1-ND, Tolerance=1%
U4: library part ViperGanxxx, "Advanced quasi-resonant offline high voltage converter with E-mode GaN HEMT.", Manufacturer=STMicroelectronics, Package=QFN5x6
U5: library part Optoisolator1, "Optocoupler DC-IN 1-CH Transistor DC-OUT 4-Pin PDIP SMD Black T/R", Case/Package=DIP, Collector Emitter Saturation Voltage=200mV, Current Transfer Ratio=160%, Forward Current=50mA, Forward Voltage=1.2V, Isolation Voltage=5kV, Manufacturer="Taiwan Semiconductor", Manufacturer Part Number="TPC817A C9G", Max Operating Temperature=100°C, Max Output Voltage=80V, Max Power Dissipation=200mW, Min Operating Temperature=-40°C, Output Voltage=70V, Package Quantity=1000, Reverse Breakdown Voltage=6V, Supplier Part Number 1=821-TPC817AC9G
V+ V-: library part Pin_Hole

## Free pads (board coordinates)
  round 2.2 hole 1.3: 2(38.1,21) 2(38.1,31)

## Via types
v1: diameter 0.508, hole 0.305, Top Layer to Bottom Layer, 157 vias

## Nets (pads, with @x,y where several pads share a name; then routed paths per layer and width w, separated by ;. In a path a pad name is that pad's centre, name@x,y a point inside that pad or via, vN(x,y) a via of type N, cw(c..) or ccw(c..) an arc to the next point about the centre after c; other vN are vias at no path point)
Aux: D5.A R37.1 R38.1 T1.5 | length 35.1
  Top Layer w0.762: v1(48.4,28.702) v1(49.276,28.702) 50.546,27.432 50.546,20.193 51.308,19.431 51.308,14.351 50.546,13.589 50.546,12.7 51.435,11.811 54.885,11.811 55.52,11.176 T1.5@56.007,11.176
  Bottom Layer w0.254: R37.1@44.704,26.365 44.704,27.485 45.921,28.702 v1(48.4,28.702) v1@48.514,28.702 ; v1(49.276,28.702) 49.352,28.702 50.419,27.635 R38.1@50.546,27.635 ; T1.5@56.007,11.176 56.261,10.922 59.563,10.922 D5.A@59.69,11.049
Drain_SR: C11.2 Q3.D R18.1 T1.11 T1.12 | length 20.1
  Top Layer w0.254: T1.11@86.487,28.956 T1.11@86.614,28.829 ; T1.12@86.487,34.036 87.63,32.893 Q3.D@94.234,32.893
  Bottom Layer w0.254: C11.2@84.77,31.623 86.418,31.623 86.487,31.554 ; T1.12@86.487,34.036 86.487,31.554 ; T1.11@86.571,28.872 T1.11@86.487,28.956 86.487,31.554 ; Q3.D@94.453,32.674 Q3.D@94.234,32.893 98.476,32.893 R18.1@98.603,33.02
Drain_Viper: D3.A T1.4 U4.15 U4.16 | length 10.9
  Bottom Layer w0.254: U4.16@50.19,15.296 U4.15@50.19,15.796 50.49,15.796 50.513,15.773 50.513,15.643 50.662,15.494 54.718,15.494 55.48,16.256 D3.A@60.071,16.256
FB: C26.2 U4.10 U5.4 | length 31.8
  Top Layer w0.762: v1@48.766,23.2 48.766,22.417 48.76,22.411 v1(48.76,22.405) 49.403,21.762 49.403,19.558 50.165,18.796 50.165,14.859 49.403,14.097 49.403,11.938 50.546,10.795 52.324,10.795 54.731,8.388 61.716,8.388 63.309,6.794 v1(63.309,6)
  Bottom Layer w0.254: v1(48.76,22.405) 48.775,22.39 48.775,20.911 U4.10@48.79,20.896 ; v1@48.76,23.14 48.76,24.388 C26.2@48.768,24.396
  other v1: 63.309,6.9 48.772,23.2
GND-Out: C8.1 C25.1 C27.1 C28.1 DZ3.A P1.2 R14.2 R15.2 R16.2 R23.2 R29.1 R43.2 U2.3 U2.4 U3.3 U5.2 U6.4 V-.1 | length 126.9
  Top Layer w0.254: P1.2@97.73,1.778 100.143,4.191 104.267,4.191 105.664,2.794 108.458,2.794 108.48,2.772 108.69,2.772 114.808,8.89 V-.1@118.618,8.89
  Bottom Layer w0.254: v1(73.148,1.524) v1(74.164,1.524) ; U5.2@73.787,3.048 73.787,1.905 74.164,1.528 v1(74.164,1.524) ; v1(76.835,7.747) v1(75.946,7.747) 75.946,6.223 75.946,4.699 76.073,4.572 ; U2.3@81.42,5.207 U2.4@81.42,6.477 ; R43.2@81.458,8.382 81.42,8.344 U2.4@81.42,6.477 ; C25.1@90.412,2.667 90.412,1.746 ; U3.3@93.406,8.509 94.869,8.509 DZ3.A@95.377,8.001 ; v1(93.956,2.66) 93.98,2.637 93.98,1.524 ; DZ3.A@95.885,8.485 96.012,8.358 96.014,8.358 96.437,7.935 96.437,7.576 ; U6.4@103.251,8.014 103.251,7.214 102.628,6.591 C27.1@102.628,5.588 102.667,5.549 R29.1@102.667,3.937 102.667,3.81 102.54,3.937 98.679,3.937 97.73,2.988 97.73,1.778 97.476,1.524 95.885,1.524 ; C28.1@105.422,14.986 104.382,14.986 103.62,14.986 103.071,14.986 99.134,11.049 97.409,11.049 96.598,10.238 v1(96.598,7.309) 96.598,5.891 97.282,5.207 97.282,2.921 95.885,1.524 ; R23.2@114.173,9.398 114.173,9.906 V-.1@118.618,9.906 ; v1(74.164,1.524) 74.549,1.524 75.516,2.491 75.516,3.017 75.692,3.193 v1(75.692,3.937) 76.073,4.318 76.073,4.572 ; 76.073,4.572 76.073,4.699 76.073,6.223 76.962,7.112 80.502,7.112 80.651,6.963 80.651,6.637 80.811,6.477 U2.4@81.42,6.477 ; U2.4@81.42,6.477 83.312,6.477 83.82,5.969 83.82,1.8 83.969,1.651 90.317,1.651 90.412,1.746 ; 90.412,1.746 90.634,1.524 93.98,1.524 ; 93.98,1.524 95.885,1.524
  Bottom Layer w0.762: V-.1@118.185,9.323 V-.1@118.618,8.89 ; C8.1@118.618,6.846 V-.1@118.618,8.89 ; R16.2@119.583,23.114 119.583,19.304 119.583,14.732 119.583,13.716 119.101,13.233 119.101,9.373 V-.1@118.618,8.89
  other v1: 75.62,3.017 80.605,7.105 100.191,11.556 101.842,13.461 103.62,14.858 104.5,14.858 79.828,15.481 80.844,15.481 81.86,15.481
GND-prim: BD1.4 C4.1 C5.1 C12.1 C16.1 C17.1 C18.1 C20.1 C21.1 C22.1 C23.1 C26.1 DZ1.A R9.2 R40.1 R44.2 R45.2 T1.6 U4.1 U4.2 U4.3 U4.4 U4.7 U4.EP U5.3 | length 162.9
  Top Layer w0.254: v1(40.767,14.986) v1(40.767,19.558) 43.815,19.558 ; 43.053,8.89 v1@43.434,8.89 ; v1(47.752,27.686) 44.831,27.686 43.815,26.67 v1(43.815,22.098) 43.815,19.558 ; v1(50.339,9.609) 49.62,8.89 v1@43.434,8.89 ; v1@50.423,6.984 56.01,1.397 v1@64.389,1.397 ; v1@43.434,8.89 43.434,19.177 43.815,19.558
  Bottom Layer w0.254: BD1.4@24.638,19.558 29.718,14.478 29.718,8.636 32.258,6.096 35.149,6.096 ; R9.2@35.052,7.061 35.052,6.193 35.149,6.096 ; v1(40.767,14.986) 40.005,14.986 39.382,15.609 C23.1@39.382,16.256 39.382,17.868 39.501,17.987 39.501,18.673 40.381,19.553 40.762,19.553 v1(40.767,19.558) ; 43.053,8.128 43.053,6.973 C5.1@43.168,6.858 ; v1(43.815,22.098) C22.1@45.224,22.098 ; C22.1@45.29,22.098 U4.7@45.29,20.296 45.998,20.296 46.617,19.677 46.617,19.169 U4.EP@46.99,18.796 ; R44.2@46.99,26.365 47.644,26.365 ; v1(47.752,27.686) 47.752,26.473 47.644,26.365 ; v1(47.752,30.353) v1(49.808,30.353) 51.932,30.353 52.053,30.232 52.133,30.232 52.451,29.914 52.451,24.435 51.765,23.749 R45.2@51.765,23.622 52.578,23.622 53.086,23.114 C21.1@53.086,21.082 ; C18.1@48.667,11.176 C17.1@48.667,7.874 48.667,7.074 48.99,6.751 50.479,6.751 51.278,5.952 51.943,5.952 ; C26.1@48.768,25.896 48.299,26.365 47.644,26.365 ; DZ1.A@51.942,4.572 51.942,5.951 51.943,5.952 ; C21.1@53.074,21.082 53.582,20.574 C20.1@53.582,19.304 53.34,19.062 53.34,18.542 53.086,18.288 48.768,18.288 48.26,18.796 U4.EP@46.99,18.796 ; C12.1@55.626,3.871 55.684,3.871 56.007,4.194 T1.6@56.007,6.096 55.863,5.952 51.943,5.952 ; v1@64.389,1.397 64.389,2.54 64.135,2.794 U5.3@64.389,3.048 66.294,3.048 66.548,3.302 66.548,7.526 66.399,7.675 66.176,7.675 65.628,8.223 C16.1@65.628,9.398 ; C16.1@65.374,10.414 C16.1@65.628,10.16 ; 35.149,6.096 38.04,6.096 C4.1@38.1,6.156 38.1,8.636 44.737,15.273 45.267,15.273 U4.1@45.29,15.296 U4.2@45.29,16.296 U4.3@45.29,17.296 U4.4@45.29,18.296 46.49,18.296 U4.EP@46.99,18.796
  other v1: 64.325,1.397 65.151,1.397 50.339,6.9 51.228,6.9 50.339,7.831 51.228,7.831 42.799,8.89 43.65,8.89 51.228,9.609 42.799,9.75 43.65,9.75 46.482,16.425 47.341,16.425 46.482,17.229 47.341,17.229 46.482,18.034 47.341,18.034 48.2,18.034 46.482,18.839 47.341,18.839 48.2,18.839 46.482,19.643 47.341,19.643 48.2,19.643 53.103,22.056 52.468,28.787 45.212,30.353 46.482,30.353 51.863,30.353
GND-Sec: C6.2 C7.2 C13.1 C14.1 C16.2 Q3.S R14.1 R15.1 R16.1 R21.2 R25.2 R27.2 R28.2 R31.1 U1.1 U1.3 | length 152
  Top Layer w0.254: v1(98.488,10.16) v1(99.441,10.16) 104.267,10.16 106.172,12.065 v1@113.157,12.065
  Bottom Layer w0.254: C16.2@71.278,9.398 C16.2@71.778,9.898 ; R27.2@75.819,35.874 79.756,35.874 80.479,36.597 81.682,36.597 82.169,37.084 92.383,37.084 Q3.S@94.034,35.433 ; R31.1@98.806,8.839 98.732,8.914 99.441,9.623 v1(99.441,10.16) ; U1.3@106.299,28.765 106.312,28.778 106.312,29.858 106.68,30.226 108.69,30.226 108.839,30.077 ; U1.1@108.839,28.765 108.839,30.077 ; v1@113.157,12.065 113.792,12.065 v1@113.919,11.938 ; 114.681,12.319 114.3,11.938 v1@113.919,11.938 ; Q3.S@94.034,35.433 Q3.S@94.234,35.433 96.266,35.433 98.74,37.907 C14.1@103.378,37.907 108.27,37.907 108.915,37.262 R21.2@108.915,36.068 108.915,36.043 109.195,35.763 R25.2@110.871,35.763 110.91,35.802 C13.1@112.649,35.802 113.804,35.802 114.3,35.306 114.3,33.274 113.665,32.639 111.904,32.639 110.871,32.639 108.839,30.607 108.839,30.077 ; Q3.S@94.034,35.433 91.694,35.433 90.297,34.036 90.297,25.654 92.115,23.836 C6.2@96.266,23.836 96.286,23.856 107.676,23.856 C7.2@107.696,23.876 112.827,23.876 113.589,23.114 113.589,19.304 113.589,14.732 113.589,12.649 113.919,12.319 113.919,12.065 v1@113.919,11.938
  Bottom Layer w0.762: C16.2@71.278,9.398 71.278,11.969 83.312,24.003 88.646,24.003 90.297,25.654
  other v1: 113,12 113.84,12 114.681,12 110.236,27.94 110.236,28.75 111.887,31.15 111.904,31.955 111.904,32.759 114.063,37.077 105.537,37.592 110.363,37.846 111.342,37.846 112.322,37.846 113.301,37.846 104.902,38.1 106.2,38.1
HV: C22.2 R22.2 U4.8 | length 15.2
  Bottom Layer w0.254: R22.2@43.307,32.512 42.672,31.877 42.672,24.13 43.18,23.622 45.974,23.622 46.736,22.86 46.736,22.152 46.79,22.098 U4.8@46.79,20.896
In-: R30.2 R31.2 R34.1 R48.1 U2.2 | length 33.5
  Top Layer w0.635: v1(79.121,5.969) 83.439,1.651 94.742,1.651 95.786,2.695 v1(95.786,3.955) 96.538,3.955 v1(98.806,6.223)
  Bottom Layer w0.254: v1(79.121,5.969) 79.096,5.944 79.096,4.978 R30.2@78.816,4.699 78.816,4.572 79.451,3.937 U2.2@81.42,3.937 ; R34.1@94.488,3.773 R34.1@94.488,3.988 94.52,3.955 v1(95.786,3.955) ; v1(98.806,6.223) 98.806,7.417 R48.1@101.092,7.417
NetBD1_2: BD1.2 C1.1 L1.3 | length 19.4
  Bottom Layer w0.254: L1.3@16.336,29.638 L1.3@16.256,29.558 16.129,29.685 16.129,34.544 17.018,35.433 19.819,35.433 C1.1@19.946,35.306 19.946,30.473 20.955,29.464 24.384,29.464 BD1.2@24.638,29.718
NetBD1_3: BD1.3 C1.2 L1.4 R5.1 | length 47.2
  Bottom Layer w0.254: L1.4@6.256,29.304 6.256,34.638 5.855,35.039 5.213,35.039 C1.2@4.946,35.306 3.302,35.306 2.032,34.036 2.032,26.67 3.81,24.892 24.384,24.892 BD1.3@24.638,24.638 24.765,24.765 26.289,24.765 27.94,26.416 R5.1@29.972,26.416
NetC2_1: C2.1 L1.2 NTC1.2 R1.1 RV1.2 | length 25.6
  Bottom Layer w0.254: L1.2@16.256,19.558 19.699,16.115 C2.1@19.699,13.589 ; R1.1@18.346,11.557 18.346,11.684 19.686,13.024 19.686,13.576 C2.1@19.699,13.589 ; RV1.2@19.558,6.223 22.225,6.223 NTC1.2@25.273,9.271 25.146,9.398 25.146,11.176 22.479,13.843 C2.1@19.953,13.843 19.764,13.654 C2.1@19.699,13.589
NetC2_2: C2.2 F1.2 L1.1 R7.2 RV1.1 | length 26.8
  Bottom Layer w0.254: F1.2@4.826,7.493 4.841,7.508 12.043,7.508 RV1.1@12.058,7.523 12.058,7.627 10.668,9.017 6.477,9.017 4.953,10.541 4.953,11.43 ; L1.1@6.256,19.558 4.953,18.255 C2.2@4.953,13.843 4.953,11.43 ; R7.2@6.553,11.43 4.953,11.43
NetC3_1: C3.1 C4.2 pad.2@38.1,21 R4.1 R6.2 R8.1 | length 24.1
  Bottom Layer w0.254: R6.2@34.417,20.32 36.83,20.32 ; R8.1@35.052,13.716 35.052,14.351 ; R4.1@35.052,23.571 36.373,23.571 36.83,23.114 ; C4.2@38.1,13.656 37.995,13.656 37.3,14.351 35.052,14.351 ; 38.1,23.114 C3.1@38.1,25.46 36.83,24.19 36.83,23.114 ; 35.052,14.351 35.052,14.783 36.83,14.783 36.83,20.32 ; 36.83,20.32 36.83,23.114
NetC5_2: C5.2 DZ1.K Q2.B R24.1 | length 14.3
  Top Layer w0.762: v1(41.529,8.001) 42.608,6.921 46.038,6.921 47.117,5.842 v1(47.117,4.953)
  Bottom Layer w0.254: v1(41.529,8.001) 41.529,7.321 41.402,7.194 41.703,6.893 41.668,6.858 41.68,6.846 Q2.B@41.68,5.08
  Bottom Layer w0.762: v1(47.117,4.953) 48.473,4.953 DZ1.K@48.642,4.784 ; R24.1@48.641,2.489 DZ1.K@48.642,4.657
NetC9_1: C9.1 C10.1 R11.2 R12.2 R13.2 R17.1 | length 19.3
  Bottom Layer w0.254: 65.304,19.685 R17.1@68.58,19.685 ; C9.1@65.304,20.066 65.304,22.606 66.04,22.606 66.815,23.381 66.815,26.162 66.815,30.607 R13.2@66.815,35.052
NetC11_1: C11.1 R27.1 R28.1 | length 7.7
  Bottom Layer w0.254: R27.1@75.819,30.674 79.756,30.674 82.248,30.674 82.997,31.423 C11.1@82.997,31.623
